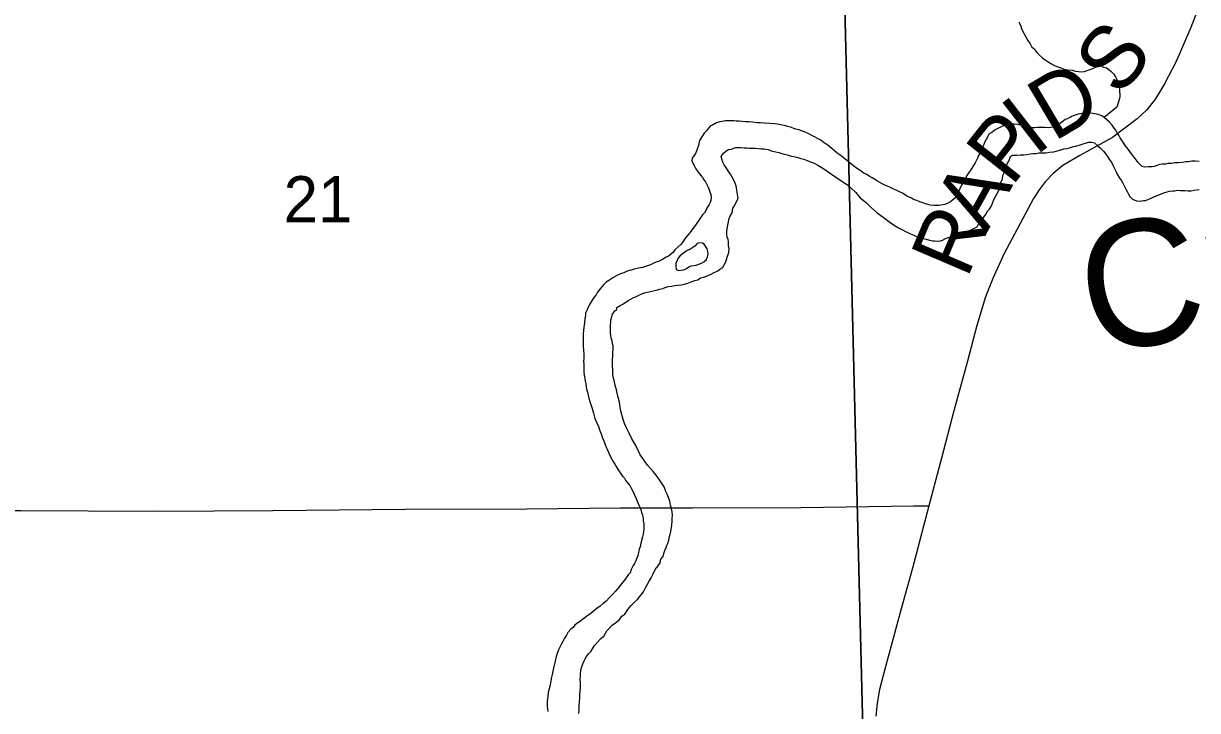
# Model space of a CAD drawing. Extents: x 10.6 to 44.6, y -2.6 to 23.4.
# Drawn here: x 15.478 to 16.54, y 19.869 to 20.49 of the extents above; entities that cross this region are included whole.
import ezdxf

# ---------------------------------------------------------------- set-up
doc = ezdxf.new("R2010")
doc.units = 0
for name, color, linetype in [('GM_X_County_Road', 7, 'Continuous'), ('GM_X_County_Road_Text', 7, 'Continuous'), ('GM_X_Major_River', 7, 'Continuous'), ('GM_X_Major_River_Text', 7, 'Continuous'), ('GM_X_Minor_River', 7, 'Continuous'), ('GM_X_Section', 7, 'Continuous'), ('GM_X_Section_Text', 7, 'Continuous'), ('GM_X_Township_Road', 7, 'Continuous')]:
    doc.layers.add(name, color=color, linetype=linetype)

msp = doc.modelspace()

# ---------------------------------------------------------------- linework, layer by layer
at = {"layer": 'GM_X_County_Road'}
msp.add_lwpolyline([(16.5614, 20.5565), (16.5343, 20.4862), (16.521, 20.4554), (16.5105, 20.4353), (16.5023, 20.4215), (16.4943, 20.4113), (16.4856, 20.4035), (16.4633, 20.3868), (16.4339, 20.3703), (16.4184, 20.3613), (16.4097, 20.3541), (16.4024, 20.3465), (16.3971, 20.3395), (16.392, 20.3315), (16.3651, 20.2811), (16.3551, 20.2593), (16.3486, 20.2425), (16.3408, 20.2166), (16.3321, 20.1844), (16.3199, 20.1395), (16.3088, 20.0968), (16.2972, 20.0535), (16.2825, 19.9974), (16.2723, 19.9604), (16.2573, 19.9059), (16.2527, 19.8874), (16.2504, 19.8752), (16.2492, 19.8634)], dxfattribs=at)
at = {"layer": 'GM_X_Major_River'}
for points in [[(16.5417, 20.3649), (16.5382, 20.3652), (16.5352, 20.3652), (16.5322, 20.3647), (16.5299, 20.3647), (16.5265, 20.3642), (16.5231, 20.3638), (16.5196, 20.3637), (16.517, 20.3632), (16.5136, 20.3632), (16.5113, 20.3627), (16.5086, 20.3627), (16.506, 20.3622), (16.503, 20.361), (16.5011, 20.3606), (16.4992, 20.3602), (16.4957, 20.3601), (16.4923, 20.36), (16.4904, 20.3604), (16.4865, 20.3641), (16.4838, 20.3678), (16.4807, 20.3719), (16.4775, 20.3761), (16.4752, 20.379), (16.4705, 20.3865), (16.4693, 20.3888), (16.4677, 20.391), (16.4665, 20.3933), (16.4649, 20.3952), (16.463, 20.3978), (16.4606, 20.4004), (16.4583, 20.4026), (16.456, 20.4049), (16.4537, 20.4063), (16.4506, 20.4074), (16.4475, 20.4081), (16.4456, 20.4084), (16.4434, 20.4088), (16.4414, 20.4087), (16.4388, 20.4087), (16.4369, 20.4086), (16.4346, 20.4082), (16.4323, 20.4078), (16.4304, 20.4073), (16.427, 20.4061), (16.4252, 20.4049), (16.4225, 20.4037), (16.4206, 20.4029), (16.4188, 20.4014), (16.4147, 20.3983), (16.4117, 20.3967), (16.409, 20.3959), (16.4056, 20.3954), (16.4022, 20.3957), (16.3987, 20.3956), (16.3957, 20.3956), (16.393, 20.3955), (16.3911, 20.3955), (16.3892, 20.3958), (16.382, 20.3975), (16.3789, 20.3982), (16.377, 20.3986), (16.3751, 20.3985), (16.3732, 20.3989), (16.3701, 20.3984)], [(16.119, 20.4017), (16.1152, 20.4016), (16.1133, 20.4016), (16.1103, 20.4011), (16.108, 20.4007), (16.105, 20.3999), (16.1016, 20.3979), (16.0997, 20.3971), (16.0978, 20.3952), (16.096, 20.3928), (16.0938, 20.3905), (16.0897, 20.384), (16.0887, 20.3794), (16.0862, 20.3721), (16.0832, 20.3679), (16.0829, 20.3652), (16.0849, 20.3614), (16.0865, 20.3584), (16.0884, 20.3554), (16.0908, 20.3524), (16.0923, 20.3506), (16.0935, 20.3483), (16.0951, 20.3465), (16.0963, 20.3442), (16.0975, 20.3419), (16.0987, 20.3386), (16.0999, 20.3352), (16.1003, 20.3325), (16.1, 20.3298), (16.0993, 20.3279), (16.0986, 20.326), (16.0967, 20.3233), (16.0956, 20.3214), (16.0942, 20.3187), (16.0923, 20.3168), (16.0897, 20.3129), (16.0886, 20.311), (16.086, 20.3075), (16.0838, 20.3044), (16.082, 20.3017), (16.0805, 20.2998), (16.0771, 20.2959), (16.0753, 20.2932), (16.0731, 20.2901), (16.0701, 20.2874), (16.0675, 20.285), (16.066, 20.2827), (16.0634, 20.2808), (16.0615, 20.2792), (16.0596, 20.2784), (16.0563, 20.2764), (16.0532, 20.2749), (16.0514, 20.2741), (16.0491, 20.2732), (16.0453, 20.2716), (16.0419, 20.2704), (16.04, 20.2696), (16.0381, 20.2692), (16.0363, 20.2688), (16.0344, 20.2684), (16.0321, 20.2679), (16.0302, 20.2675), (16.0283, 20.2667), (16.026, 20.2663), (16.0238, 20.2655), (16.0211, 20.2643), (16.0181, 20.2635), (16.0155, 20.2623), (16.0113, 20.2599), (16.0095, 20.2587), (16.0076, 20.2575), (16.0053, 20.256), (16.0027, 20.2536), (16.0012, 20.2517), (15.9998, 20.2498), (15.9975, 20.2467), (15.9961, 20.2444), (15.9942, 20.242), (15.9916, 20.2382), (15.9898, 20.2351), (15.9891, 20.2332), (15.988, 20.2309), (15.9865, 20.2278), (15.9866, 20.2251), (15.9859, 20.2229), (15.9856, 20.219), (15.9852, 20.2171), (15.9849, 20.2152), (15.9846, 20.2118), (15.9843, 20.2095), (15.9843, 20.2076), (15.9844, 20.2042), (15.9844, 20.2023), (15.9845, 20.2004), (15.9845, 20.1977), (15.9846, 20.1943), (15.985, 20.1909), (15.9851, 20.1886), (15.9851, 20.1867), (15.9848, 20.1844), (15.9849, 20.1818)], [(16.3701, 20.3984), (16.3671, 20.398), (16.3649, 20.3972), (16.3626, 20.3964), (16.3603, 20.3952), (16.3573, 20.3936), (16.3543, 20.3912), (16.3517, 20.39), (16.351, 20.3881), (16.3491, 20.385), (16.348, 20.3827), (16.3469, 20.3804), (16.3462, 20.3785), (16.3455, 20.3766), (16.3441, 20.3735), (16.3422, 20.3705), (16.3415, 20.3685), (16.3404, 20.3662), (16.3393, 20.3639), (16.3371, 20.3605), (16.3353, 20.3574), (16.3334, 20.3551), (16.3316, 20.3524), (16.3294, 20.3478), (16.3279, 20.3454), (16.3268, 20.3435), (16.325, 20.3397), (16.3232, 20.3366), (16.3221, 20.3339), (16.321, 20.332), (16.3169, 20.3285), (16.3139, 20.3269), (16.3116, 20.3261), (16.3063, 20.3252), (16.304, 20.3252), (16.3017, 20.3251), (16.2983, 20.3254), (16.2964, 20.3261), (16.2941, 20.3268), (16.2918, 20.3276), (16.2891, 20.3286), (16.2864, 20.3297), (16.2841, 20.3304), (16.2814, 20.3319), (16.2772, 20.3337), (16.2753, 20.3352), (16.2733, 20.3363), (16.2706, 20.3374), (16.2683, 20.3388), (16.2656, 20.3399), (16.2626, 20.3414), (16.2603, 20.3424), (16.258, 20.3432), (16.2557, 20.3446), (16.253, 20.3461), (16.2507, 20.3472), (16.2483, 20.3486), (16.246, 20.3501), (16.2433, 20.3516), (16.241, 20.3531), (16.2383, 20.3545), (16.2364, 20.356), (16.2341, 20.3575), (16.2318, 20.3589), (16.2294, 20.3608), (16.226, 20.3634), (16.2229, 20.366), (16.2198, 20.3685), (16.2171, 20.3708), (16.2144, 20.3726), (16.2074, 20.3785), (16.2051, 20.38), (16.2016, 20.3826), (16.1996, 20.3844), (16.1966, 20.3859), (16.1943, 20.387), (16.192, 20.3881), (16.1885, 20.3899), (16.1847, 20.3917), (16.182, 20.3928), (16.1797, 20.3935), (16.177, 20.3942), (16.1751, 20.3949), (16.172, 20.396), (16.1693, 20.3967), (16.1667, 20.3974), (16.1644, 20.3977), (16.1617, 20.3984), (16.1579, 20.3991), (16.1533, 20.3994), (16.1483, 20.3997), (16.1449, 20.4), (16.1415, 20.3999), (16.1381, 20.4006), (16.1346, 20.4009), (16.1312, 20.4008), (16.1282, 20.4011), (16.1255, 20.4015), (16.1228, 20.4014), (16.1209, 20.4017), (16.119, 20.4017)], [(16.0856, 20.2573), (16.0882, 20.2581), (16.0905, 20.2597), (16.0935, 20.2605), (16.0961, 20.2614), (16.098, 20.2622), (16.1003, 20.263), (16.1025, 20.2642), (16.1063, 20.2661), (16.1082, 20.2677), (16.1108, 20.2693), (16.1134, 20.2743), (16.1148, 20.2785), (16.1162, 20.2827), (16.1165, 20.2861), (16.1161, 20.2891), (16.116, 20.2926), (16.1156, 20.2945), (16.1148, 20.2967), (16.1144, 20.299), (16.1143, 20.3024), (16.115, 20.3055), (16.1153, 20.3074), (16.116, 20.3104), (16.1167, 20.3135), (16.1174, 20.3154), (16.1193, 20.3185), (16.1199, 20.3227), (16.1214, 20.325), (16.1225, 20.3277), (16.124, 20.3304), (16.1247, 20.3323), (16.1242, 20.3349), (16.1238, 20.3372), (16.1234, 20.3391), (16.1233, 20.341), (16.1229, 20.3429), (16.1221, 20.3455), (16.1209, 20.3482), (16.1193, 20.3508), (16.1178, 20.3534), (16.1162, 20.3557), (16.1134, 20.3598), (16.1119, 20.362), (16.1107, 20.3643), (16.1099, 20.3673), (16.1094, 20.3696), (16.1113, 20.3726), (16.1135, 20.3742), (16.1161, 20.3758), (16.1188, 20.3762), (16.1207, 20.377), (16.1226, 20.3775), (16.1249, 20.3775), (16.1275, 20.3776), (16.1302, 20.3772), (16.1328, 20.3773), (16.1351, 20.377), (16.1374, 20.377), (16.1405, 20.3771), (16.1431, 20.3768), (16.1454, 20.3764), (16.1481, 20.3765), (16.15, 20.3761), (16.1519, 20.3758), (16.1554, 20.3744), (16.1588, 20.3737), (16.1615, 20.373), (16.1641, 20.3723), (16.1664, 20.3716), (16.1691, 20.3709), (16.1718, 20.3702), (16.1749, 20.3695), (16.1779, 20.3688), (16.1814, 20.3677), (16.184, 20.367), (16.1871, 20.3659), (16.1909, 20.3645), (16.1936, 20.3634), (16.1967, 20.3616), (16.2013, 20.359), (16.206, 20.3557), (16.2114, 20.352), (16.2237, 20.3439), (16.2272, 20.3406), (16.2311, 20.3369), (16.235, 20.332), (16.2408, 20.3276), (16.2455, 20.3231), (16.2505, 20.3187), (16.2559, 20.3146), (16.2606, 20.3109), (16.2652, 20.3076), (16.2698, 20.305), (16.2733, 20.3032), (16.276, 20.3018), (16.2783, 20.3007), (16.2806, 20.2996), (16.2836, 20.2985), (16.2867, 20.297), (16.2909, 20.2956)], [(16.2909, 20.2956), (16.2948, 20.2946), (16.2978, 20.2939), (16.3005, 20.2932), (16.3028, 20.2932), (16.3058, 20.2929), (16.3077, 20.2933), (16.3096, 20.2937), (16.3122, 20.2953), (16.3187, 20.2974), (16.3232, 20.2986), (16.3262, 20.2994), (16.3281, 20.3002), (16.33, 20.3006), (16.3334, 20.3022), (16.336, 20.3034), (16.3387, 20.3046), (16.3409, 20.3058), (16.3424, 20.3089), (16.3446, 20.3124), (16.3468, 20.3143), (16.3487, 20.317), (16.3501, 20.3197), (16.352, 20.322), (16.3535, 20.3243), (16.3546, 20.3263), (16.356, 20.3305), (16.3608, 20.3393), (16.3618, 20.3424), (16.3625, 20.3462), (16.364, 20.3489), (16.3643, 20.3523), (16.3654, 20.3546), (16.3668, 20.3596), (16.3682, 20.363), (16.3697, 20.3654), (16.3711, 20.3696), (16.373, 20.3707), (16.3768, 20.3708), (16.3802, 20.3709), (16.3833, 20.371), (16.3863, 20.3714), (16.389, 20.3719), (16.3916, 20.3723), (16.3943, 20.3723), (16.3969, 20.3728), (16.3996, 20.3728), (16.403, 20.3729), (16.4064, 20.3734), (16.4102, 20.3738), (16.4133, 20.3747), (16.4159, 20.3751), (16.4193, 20.3763), (16.4223, 20.3768), (16.4246, 20.3772), (16.428, 20.3784), (16.4303, 20.3788), (16.4341, 20.3801), (16.436, 20.3805), (16.4386, 20.3817), (16.442, 20.3825), (16.4443, 20.3826), (16.447, 20.3819), (16.4505, 20.3789), (16.4524, 20.3774), (16.4555, 20.3741), (16.4571, 20.3718), (16.459, 20.3696), (16.4606, 20.3666), (16.4626, 20.3643), (16.4638, 20.3617), (16.465, 20.3591), (16.4665, 20.3561), (16.4677, 20.3534), (16.4697, 20.35), (16.4713, 20.3482), (16.4725, 20.3459), (16.4736, 20.3437), (16.4756, 20.3399), (16.4768, 20.3377), (16.478, 20.3354), (16.4792, 20.3332), (16.4815, 20.3309), (16.485, 20.3295), (16.4884, 20.3292), (16.4914, 20.3296), (16.4933, 20.3297), (16.4964, 20.3309), (16.4983, 20.3317), (16.5009, 20.3329), (16.5107, 20.3369), (16.5149, 20.3381), (16.5179, 20.3386), (16.5198, 20.3386), (16.5221, 20.339), (16.5251, 20.3387), (16.5289, 20.3388), (16.532, 20.3385), (16.5346, 20.3385), (16.5373, 20.339), (16.5418, 20.3398)], [(16.0938, 20.2902), (16.0923, 20.2911), (16.09, 20.2915), (16.0877, 20.2907), (16.0855, 20.2884), (16.081, 20.2853), (16.0787, 20.2845), (16.0742, 20.2814), (16.0719, 20.2795), (16.0701, 20.2772), (16.0693, 20.2749), (16.0682, 20.2726), (16.0682, 20.2703), (16.0687, 20.2673)], [(16.0687, 20.2673), (16.0709, 20.2665), (16.0732, 20.2666), (16.0755, 20.267), (16.0778, 20.2682), (16.08, 20.2697), (16.0823, 20.2705), (16.0868, 20.2713), (16.0891, 20.2721), (16.0914, 20.2729), (16.0936, 20.2741), (16.0959, 20.2764), (16.097, 20.2787), (16.0977, 20.2813), (16.0973, 20.2836), (16.0965, 20.2859), (16.0938, 20.2902)], [(16.0497, 19.9959), (16.0523, 19.9993), (16.0541, 20.002), (16.0548, 20.0055), (16.0567, 20.0078), (16.0574, 20.0105), (16.0584, 20.0131), (16.0595, 20.0158), (16.0602, 20.0177), (16.061, 20.0197), (16.062, 20.0227), (16.0627, 20.0258), (16.0634, 20.0288), (16.0641, 20.0323), (16.0648, 20.0361), (16.0651, 20.0399), (16.065, 20.0426), (16.0654, 20.0448), (16.0649, 20.0486), (16.0645, 20.0509), (16.0636, 20.0543), (16.0628, 20.0577), (16.0616, 20.0611), (16.0604, 20.0641), (16.0592, 20.0667), (16.0576, 20.0709), (16.0552, 20.0743), (16.0529, 20.078), (16.0505, 20.0814), (16.0478, 20.0847), (16.0454, 20.0873), (16.0427, 20.0903), (16.0404, 20.0933), (16.0384, 20.0963), (16.0361, 20.0997), (16.0341, 20.1038), (16.0321, 20.1083), (16.0285, 20.1143), (16.0261, 20.1192), (16.0237, 20.1241), (16.0218, 20.1282), (16.0205, 20.1316), (16.0185, 20.1396), (16.018, 20.1426), (16.0176, 20.1453), (16.0172, 20.1475), (16.0163, 20.1506), (16.0159, 20.1528), (16.0151, 20.1555), (16.0146, 20.1585), (16.0134, 20.1626), (16.0126, 20.1668), (16.0117, 20.1702), (16.0113, 20.1729), (16.0112, 20.1751), (16.0112, 20.1774), (16.0111, 20.1797), (16.0111, 20.1827), (16.011, 20.1862), (16.0113, 20.1888), (16.0113, 20.1919), (16.0116, 20.1953), (16.0115, 20.1983), (16.0111, 20.2002), (16.0107, 20.2029), (16.0098, 20.2055), (16.0094, 20.2074), (16.0093, 20.2104), (16.0093, 20.2139), (16.0092, 20.2169), (16.0095, 20.2196), (16.0095, 20.2215), (16.0109, 20.2268), (16.0131, 20.2299), (16.015, 20.2311), (16.015, 20.233), (16.018, 20.2349), (16.0202, 20.2361), (16.0251, 20.2393), (16.027, 20.2401), (16.0304, 20.2421), (16.0326, 20.2429), (16.0349, 20.2441), (16.0375, 20.2453), (16.0398, 20.2461), (16.0424, 20.2469), (16.0455, 20.2473), (16.0477, 20.2481), (16.0504, 20.2486), (16.0538, 20.2494), (16.0564, 20.2502), (16.0587, 20.251), (16.0613, 20.2519), (16.0644, 20.2523), (16.0674, 20.2527), (16.0704, 20.2532), (16.0731, 20.2536), (16.0761, 20.2541), (16.0792, 20.2549), (16.0822, 20.2561), (16.0856, 20.2573)], [(15.9849, 20.1818), (15.9849, 20.1795), (15.985, 20.1768), (15.985, 20.1746), (15.9854, 20.1719), (15.9859, 20.1689), (15.9863, 20.1662), (15.9868, 20.164), (15.9872, 20.1617), (15.9876, 20.159), (15.9884, 20.1564), (15.9889, 20.1538), (15.9897, 20.1511), (15.9905, 20.1481), (15.9913, 20.1451), (15.9926, 20.1417), (15.9938, 20.1375), (15.995, 20.1326), (15.9982, 20.1255), (15.999, 20.1232), (15.9998, 20.1209), (16.0007, 20.1187), (16.0015, 20.1156), (16.0027, 20.113), (16.0039, 20.11), (16.0051, 20.1074), (16.0059, 20.1055), (16.0071, 20.1028), (16.0079, 20.1006), (16.0091, 20.098), (16.0107, 20.0953), (16.0119, 20.0931), (16.013, 20.0912), (16.0142, 20.0893), (16.0162, 20.0863), (16.0174, 20.0845), (16.0185, 20.0826), (16.0201, 20.0803), (16.0217, 20.0785), (16.0232, 20.0762), (16.0248, 20.074), (16.0268, 20.0721), (16.0276, 20.0702), (16.0295, 20.0669), (16.0307, 20.0642), (16.0323, 20.0601), (16.0339, 20.0563), (16.0347, 20.0541), (16.0359, 20.0518), (16.0367, 20.0499), (16.0372, 20.0476), (16.038, 20.0454), (16.0388, 20.042), (16.0388, 20.0401), (16.0393, 20.0374), (16.0393, 20.0351), (16.0394, 20.0325), (16.0391, 20.0302), (16.0387, 20.0279), (16.038, 20.0256), (16.0366, 20.0199), (16.0359, 20.0165), (16.0352, 20.0145), (16.0349, 20.0126), (16.0342, 20.0103), (16.0338, 20.0084), (16.0327, 20.0057), (16.032, 20.0038), (16.0309, 20.0015), (16.0298, 19.9996), (16.028, 19.9961), (16.0269, 19.9931), (16.0251, 19.9911), (16.0228, 19.9877), (16.0202, 19.9846), (16.018, 19.9815), (16.0158, 19.9788), (16.0136, 19.9764), (16.011, 19.9733), (16.0084, 19.9706), (16.0054, 19.9675), (16.0024, 19.9652), (15.9998, 19.9628), (15.9968, 19.9609), (15.9934, 19.9581), (15.9916, 19.9566), (15.9897, 19.955), (15.9878, 19.9538), (15.9859, 19.9523), (15.9837, 19.9507), (15.9811, 19.9488), (15.9788, 19.9472), (15.977, 19.9456), (15.9755, 19.9437), (15.9732, 19.9421), (15.9706, 19.939), (15.9695, 19.9367), (15.9677, 19.934), (15.9659, 19.9309), (15.9644, 19.9283), (15.9633, 19.9259)], [(15.9806, 19.8659), (15.9809, 19.8697), (15.9808, 19.8731), (15.9811, 19.8766), (15.9814, 19.8792), (15.9813, 19.8826), (15.9816, 19.8861), (15.982, 19.8891), (15.9819, 19.891), (15.9819, 19.8941), (15.9818, 19.8963), (15.9821, 19.8998), (15.9821, 19.902), (15.9824, 19.9039), (15.9827, 19.9066), (15.9834, 19.9089), (15.9842, 19.9108), (15.9852, 19.9135), (15.9863, 19.9154), (15.9874, 19.9174), (15.9897, 19.9201), (15.9915, 19.922), (15.993, 19.9243), (15.9948, 19.9274), (15.9978, 19.9305), (16.0004, 19.9336), (16.003, 19.9359), (16.006, 19.9406), (16.0108, 19.9456), (16.0149, 19.9487), (16.0172, 19.9507), (16.0194, 19.9538), (16.022, 19.9557), (16.025, 19.96), (16.0279, 19.9635), (16.0309, 19.9666), (16.0335, 19.9689), (16.0391, 19.9759), (16.0398, 19.9778), (16.0413, 19.9801), (16.0427, 19.9828), (16.0442, 19.9855), (16.046, 19.9886), (16.0479, 19.992), (16.0497, 19.9959)], [(15.9633, 19.9259), (15.9622, 19.9233), (15.9611, 19.921), (15.9601, 19.9175), (15.959, 19.9133), (15.9573, 19.9057), (15.9566, 19.9022), (15.9559, 19.8988), (15.9552, 19.8954), (15.9545, 19.8916), (15.9538, 19.8881), (15.9528, 19.8847), (15.9524, 19.8816), (15.9521, 19.879), (15.9518, 19.8763), (15.9518, 19.8744), (15.9519, 19.8725), (15.9523, 19.8702), (15.9524, 19.8676)]]:
    msp.add_lwpolyline(points, dxfattribs=at)
at = {"layer": 'GM_X_Minor_River'}
for points in [[(16.3788, 20.4913), (16.3796, 20.4894), (16.3804, 20.4872), (16.3812, 20.4853), (16.382, 20.483), (16.3868, 20.4744), (16.3888, 20.4714), (16.3903, 20.4684), (16.3927, 20.4669), (16.3938, 20.4651), (16.3954, 20.4632), (16.3973, 20.461), (16.4001, 20.4587), (16.4024, 20.4569), (16.4051, 20.455), (16.4082, 20.4532), (16.4109, 20.4518), (16.4132, 20.451), (16.4166, 20.4496), (16.4193, 20.4485), (16.4227, 20.4478), (16.4269, 20.4475), (16.43, 20.4468), (16.433, 20.4465), (16.4357, 20.4462), (16.438, 20.4463), (16.4414, 20.4475)], [(16.4414, 20.4475), (16.4455, 20.4491), (16.4501, 20.4511), (16.4527, 20.4519), (16.4554, 20.4504), (16.4581, 20.4497), (16.46, 20.4483), (16.4623, 20.4464), (16.4647, 20.4438), (16.4662, 20.4416), (16.467, 20.4397), (16.4683, 20.4363), (16.4691, 20.4344), (16.4695, 20.4325), (16.4699, 20.4302), (16.47, 20.4238), (16.4697, 20.4219), (16.4672, 20.4142), (16.456, 20.4049)]]:
    msp.add_lwpolyline(points, dxfattribs=at)
at = {"layer": 'GM_X_Section'}
for points in [[(17.1705, 20.912), (17.1955, 19.8385), (16.2385, 19.8158), (16.2115, 20.8899), (16.6813, 20.903), (17.1521, 20.9117)], [(16.2115, 20.8899), (16.2385, 19.8158), (15.2731, 19.8042), (15.2724, 20.0685), (15.2585, 20.8662), (15.7344, 20.8781), (16.2067, 20.8898)]]:
    msp.add_lwpolyline(points, close=True, dxfattribs=at)
at = {"layer": 'GM_X_Township_Road'}
msp.add_lwpolyline([(15.2699, 20.0496), (15.3316, 20.0494), (15.4215, 20.0494), (15.4757, 20.0494), (15.5974, 20.0489), (15.7037, 20.0494), (15.8234, 20.0505), (15.9334, 20.051), (16.0179, 20.0517), (16.0838, 20.0517), (16.1815, 20.0522), (16.2836, 20.0535), (16.2972, 20.0535)], dxfattribs=at)

# ---------------------------------------------------------------- texts
at = {"layer": 'GM_X_County_Road_Text'}
for s, rotation, p in [('S', 51.0698, (16.4697, 20.4222)), ('D', 30.6983, (16.4101, 20.3823)), ('I', 37.9393, (16.3933, 20.369)), ('P', 51.8129, (16.3721, 20.3414)), ('A', 61.152, (16.3494, 20.2997)), ('R', 66.8931, (16.3317, 20.2581))]:
    msp.add_text(s, height=0.0568, rotation=rotation, dxfattribs=at).set_placement(p)
at = {"layer": 'GM_X_Major_River_Text'}
msp.add_text('Creek', height=0.11371, rotation=10.388, dxfattribs=at).set_placement((16.4452, 20.1893))
at = {"layer": 'GM_X_Section_Text'}
msp.add_text('21', height=0.04186, rotation=0, dxfattribs=at).set_placement((15.7134, 20.3099))

doc.saveas('drawing.dxf')
